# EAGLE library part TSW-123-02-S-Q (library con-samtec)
THROUGH-HOLE .025" SQ POST HEADER Source: Samtec TSW.pdf
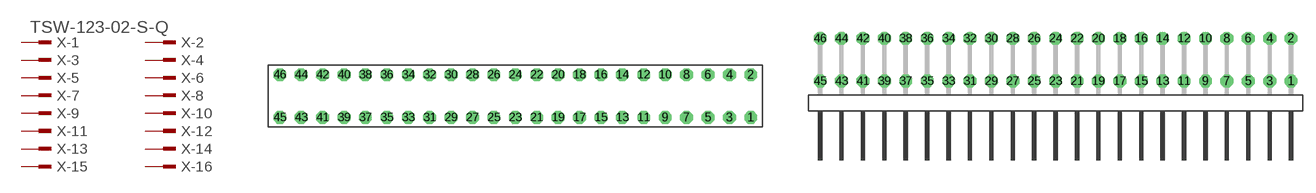
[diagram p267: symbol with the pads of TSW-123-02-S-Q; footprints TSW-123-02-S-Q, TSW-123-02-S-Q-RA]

Designator prefix X; gates -1=MPINV -2=MPIN -3=MPIN -4=MPIN -5=MPIN -6=MPIN -7=MPIN -8=MPIN -9=MPIN -10=MPIN -11=MPIN -12=MPIN -13=MPIN -14=MPIN -15=MPIN -16=MPIN -17=MPIN -18=MPIN -19=MPIN -20=MPIN -21=MPIN -22=MPIN -23=MPIN -24=MPIN -25=MPIN -26=MPIN -27=MPIN -28=MPIN -29=MPIN -30=MPIN -31=MPIN -32=MPIN -33=MPIN -34=MPIN -35=MPIN -36=MPIN -37=MPIN -38=MPIN -39=MPIN -40=MPIN -41=MPIN -42=MPIN -43=MPIN -44=MPIN -45=MPIN -46=MPIN

## TSW-123-02-S-Q (OC_FARNELL: unknown; OC_NEWARK: unknown)  [TSW-123-02-S-Q]
1  -1:1  pas
2  -2:1  pas
3  -3:1  pas
4  -4:1  pas
5  -5:1  pas
6  -6:1  pas
7  -7:1  pas
8  -8:1  pas
9  -9:1  pas
10  -10:1  pas
11  -11:1  pas
12  -12:1  pas
13  -13:1  pas
14  -14:1  pas
15  -15:1  pas
16  -16:1  pas
17  -17:1  pas
18  -18:1  pas
19  -19:1  pas
20  -20:1  pas
21  -21:1  pas
22  -22:1  pas
23  -23:1  pas
24  -24:1  pas
25  -25:1  pas
26  -26:1  pas
27  -27:1  pas
28  -28:1  pas
29  -29:1  pas
30  -30:1  pas
31  -31:1  pas
32  -32:1  pas
33  -33:1  pas
34  -34:1  pas
35  -35:1  pas
36  -36:1  pas
37  -37:1  pas
38  -38:1  pas
39  -39:1  pas
40  -40:1  pas
41  -41:1  pas
42  -42:1  pas
43  -43:1  pas
44  -44:1  pas
45  -45:1  pas
46  -46:1  pas

## TSW-123-02-S-Q-RA (OC_FARNELL: unknown; OC_NEWARK: unknown)  [TSW-123-02-S-Q-RA]
Pads as for TSW-123-02-S-Q

## Footprint TSW-123-02-S-Q (pad centres in mm)
THROUGH-HOLE .025" SQ POST HEADER Source: Samtec TSW.pdf
drill 1 pad 1.5 octagon: 1 27.94,-2.54; 2 27.94,2.54; 3 25.4,-2.54; 4 25.4,2.54; 5 22.86,-2.54; 6 22.86,2.54; 7 20.32,-2.54; 8 20.32,2.54; 9 17.78,-2.54; 10 17.78,2.54; 11 15.24,-2.54; 12 15.24,2.54; 13 12.7,-2.54; 14 12.7,2.54; 15 10.16,-2.54; 16 10.16,2.54; 17 7.62,-2.54; 18 7.62,2.54; 19 5.08,-2.54; 20 5.08,2.54; 21 2.54,-2.54; 22 2.54,2.54; 23 0,-2.54; 24 0,2.54; 25 -2.54,-2.54; 26 -2.54,2.54; 27 -5.08,-2.54; 28 -5.08,2.54; 29 -7.62,-2.54; 30 -7.62,2.54; 31 -10.16,-2.54; 32 -10.16,2.54; 33 -12.7,-2.54; 34 -12.7,2.54; 35 -15.24,-2.54; 36 -15.24,2.54; 37 -17.78,-2.54; 38 -17.78,2.54; 39 -20.32,-2.54; 40 -20.32,2.54; 41 -22.86,-2.54; 42 -22.86,2.54; 43 -25.4,-2.54; 44 -25.4,2.54; 45 -27.94,-2.54; 46 -27.94,2.54

## Footprint TSW-123-02-S-Q-RA (pad centres in mm)
THROUGH-HOLE .025" SQ POST HEADER Source: Samtec TSW.pdf
drill 1 pad 1.5 octagon: 1 27.94,1.524; 2 27.94,6.604; 3 25.4,1.524; 4 25.4,6.604; 5 22.86,1.524; 6 22.86,6.604; 7 20.32,1.524; 8 20.32,6.604; 9 17.78,1.524; 10 17.78,6.604; 11 15.24,1.524; 12 15.24,6.604; 13 12.7,1.524; 14 12.7,6.604; 15 10.16,1.524; 16 10.16,6.604; 17 7.62,1.524; 18 7.62,6.604; 19 5.08,1.524; 20 5.08,6.604; 21 2.54,1.524; 22 2.54,6.604; 23 0,1.524; 24 0,6.604; 25 -2.54,1.524; 26 -2.54,6.604; 27 -5.08,1.524; 28 -5.08,6.604; 29 -7.62,1.524; 30 -7.62,6.604; 31 -10.16,1.524; 32 -10.16,6.604; 33 -12.7,1.524; 34 -12.7,6.604; 35 -15.24,1.524; 36 -15.24,6.604; 37 -17.78,1.524; 38 -17.78,6.604; 39 -20.32,1.524; 40 -20.32,6.604; 41 -22.86,1.524; 42 -22.86,6.604; 43 -25.4,1.524; 44 -25.4,6.604; 45 -27.94,1.524; 46 -27.94,6.604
